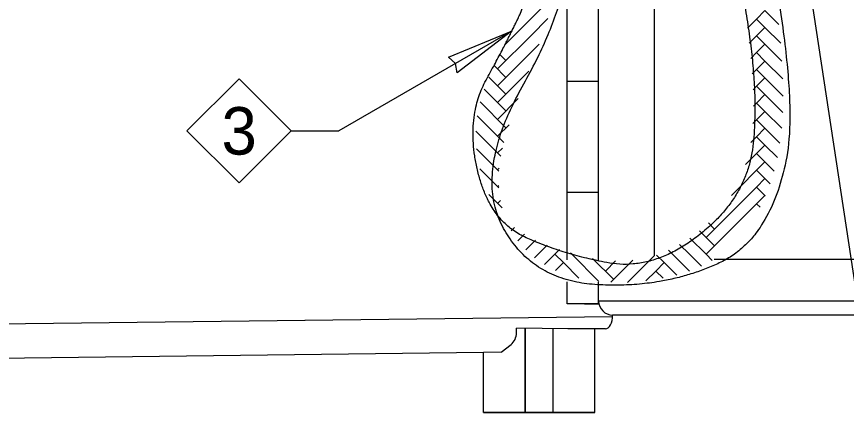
# Model space of a CAD drawing. Extents: x 99862 to 104211, y 98939 to 102076.
# Drawn here: x 100786.5 to 101065.9, y 100216.7 to 100355 of the extents above; entities that cross this region are included whole.
import ezdxf

# ---------------------------------------------------------------- set-up
doc = ezdxf.new("R2010")
doc.units = 0
for name, color, linetype in [('Level 1', 7, 'Continuous'), ('Level 12', 7, 'Continuous'), ('Level 15', 7, 'Continuous'), ('Level 16', 7, 'Continuous'), ('Level 17', 7, 'Continuous'), ('Level 20', 7, 'Continuous'), ('Level 23', 7, 'Continuous'), ('Level 3', 7, 'Continuous'), ('Level 30', 7, 'Continuous')]:
    doc.layers.add(name, color=color, linetype=linetype)

msp = doc.modelspace()

# ---------------------------------------------------------------- linework, layer by layer
at = {"layer": 'Level 1'}
for p, q in [((101001.26, 100274.46), (101001.26, 101063.37)), ((101638.77, 100273.26), (101021.35, 100273.26)), ((101657.52, 100259.2), (100982.51, 100259.2)), ((101652.84, 100254.51), (100987.19, 100254.51))]:
    msp.add_line(p, q, dxfattribs=at)
msp.add_arc((100987.19, 100259.2), 4.69, 180, 270, dxfattribs=at)
at = {"layer": 'Level 12'}
for p, q in [((100982.42, 100272.95), (100982.42, 101082.68)), ((100971.86, 100273.16), (100971.86, 100378.32)), ((100971.86, 100333.28), (100982.42, 100333.28)), ((100982.42, 100295.78), (100971.86, 100295.78)), ((100971.86, 100258.28), (100971.86, 100265.74)), ((100982.42, 100258.28), (100982.42, 100265.6)), ((100975.44, 100258.28), (100971.86, 100258.28)), ((100982.42, 100258.28), (100971.86, 100258.28)), ((100982.42, 100258.28), (100975.44, 100258.28)), ((100977.74, 100258.28), (100982.42, 100258.28))]:
    msp.add_line(p, q, dxfattribs=at)
at = {"layer": 'Level 15'}
for p, q in [((101040.62, 100450.12), (101090.56, 100120.77)), ((100953.16, 100350.13), (100894.97, 100316.54)), ((100878.97, 100316.54), (100894.97, 100316.54))]:
    msp.add_line(p, q, dxfattribs=at)
msp.add_lwpolyline([(100953.16, 100350.13), (100934.88, 100336.13), (100934.3, 100339.25), (100931.9, 100341.3)], close=True, dxfattribs=at)
at = {"layer": 'Level 16'}
for p, q in [((100965.43, 100360.01), (100959.77, 100354.35)), ((101035.67, 100354.18), (101038.5, 100357.01)), ((101043.2, 100352.3), (101038.5, 100357.01)), ((100950.81, 100345.39), (100959.77, 100354.35)), ((100965.43, 100354.35), (100959.77, 100348.7)), ((100965.43, 100354.35), (100965.44, 100354.37)), ((100965.43, 100354.35), (100965.44, 100354.34)), ((101035.67, 100354.18), (101032.6, 100351.11)), ((101035.67, 100354.18), (101038.5, 100351.35)), ((101035.67, 100348.52), (101038.5, 100351.35)), ((101043.83, 100346.02), (101038.5, 100351.35)), ((100948.46, 100337.38), (100959.77, 100348.7)), ((101035.67, 100348.52), (101033.23, 100346.08)), ((101035.67, 100348.52), (101038.5, 100345.7)), ((100962.46, 100345.73), (100959.77, 100343.04)), ((101035.67, 100342.87), (101038.5, 100345.7)), ((101044.22, 100339.97), (101038.5, 100345.7)), ((100948.46, 100331.73), (100959.77, 100343.04)), ((100951.29, 100340.21), (100949.21, 100342.29)), ((101035.67, 100342.87), (101033.76, 100340.95)), ((101035.67, 100342.87), (101038.5, 100340.04)), ((100951.29, 100334.55), (100947.33, 100338.51)), ((101035.67, 100337.21), (101038.5, 100340.04)), ((101044.53, 100334.01), (101038.5, 100340.04)), ((100948.46, 100326.07), (100959.01, 100336.62)), ((101035.67, 100337.21), (101034.18, 100335.72)), ((101035.67, 100337.21), (101038.5, 100334.38)), ((100951.29, 100328.9), (100945.56, 100334.63)), ((101035.67, 100331.55), (101038.5, 100334.38)), ((101044.62, 100328.26), (101038.5, 100334.38)), ((100951.29, 100323.24), (100943.95, 100330.58)), ((101035.67, 100331.55), (101034.5, 100330.38)), ((101035.67, 100331.55), (101038.5, 100328.73)), ((100948.46, 100320.41), (100955.45, 100327.41)), ((101035.67, 100325.9), (101038.5, 100328.73)), ((101044.49, 100322.73), (101038.5, 100328.73)), ((100951.29, 100317.58), (100942.6, 100326.27)), ((101035.67, 100325.9), (101034.61, 100324.83)), ((101035.67, 100325.9), (101038.5, 100323.07)), ((100950.56, 100312.65), (100941.62, 100321.59)), ((101035.67, 100320.24), (101038.5, 100323.07)), ((101044.13, 100317.44), (101038.5, 100323.07)), ((100948.46, 100314.76), (100952.32, 100318.62)), ((101035.67, 100320.24), (101034.41, 100318.98)), ((101035.67, 100320.24), (101038.5, 100317.41)), ((100949.54, 100308.01), (100941.15, 100316.4)), ((101035.67, 100314.58), (101038.5, 100317.41)), ((101043.55, 100312.36), (101038.5, 100317.41)), ((101035.67, 100314.58), (101033.7, 100312.61)), ((101035.67, 100314.58), (101038.5, 100311.75)), ((100948.9, 100303), (100941.36, 100310.54)), ((100948.46, 100309.1), (100950.1, 100310.74)), ((101035.67, 100308.93), (101038.5, 100311.76)), ((101042.73, 100307.52), (101038.5, 100311.76)), ((101035.67, 100308.93), (101031.97, 100305.23)), ((101035.67, 100308.93), (101038.5, 100306.1)), ((101035.67, 100303.27), (101038.5, 100306.1)), ((101041.63, 100302.97), (101038.5, 100306.1)), ((100948.88, 100297.37), (100942.48, 100303.77)), ((100948.46, 100303.44), (100948.99, 100303.97)), ((101035.67, 100303.27), (101030.01, 100297.61)), ((101035.67, 100303.27), (101038.5, 100300.44)), ((101035.67, 100297.61), (101038.5, 100300.44)), ((101040.29, 100298.65), (101038.5, 100300.44)), ((100948.46, 100297.79), (100948.84, 100298.17)), ((101027.18, 100294.78), (101030.01, 100297.61)), ((101035.67, 100297.61), (101030.01, 100291.96)), ((101035.67, 100297.61), (101038.5, 100294.78)), ((100949.97, 100290.62), (100945.5, 100295.09)), ((100948.46, 100292.13), (100949.42, 100293.09)), ((101035.67, 100291.96), (101038.5, 100294.78)), ((101038.67, 100294.61), (101038.5, 100294.78)), ((101018.7, 100280.64), (101030.01, 100291.96)), ((101035.67, 100291.96), (101030.01, 100286.3)), ((101035.67, 100291.96), (101036.83, 100290.79)), ((101018.7, 100274.99), (101030.01, 100286.3)), ((101021.53, 100283.47), (101019.46, 100285.53)), ((100953.08, 100282.91), (100954.21, 100284.03)), ((101021.53, 100277.81), (101016.46, 100282.88)), ((100955.33, 100279.5), (100957.55, 100281.72)), ((100957.96, 100276.47), (100961.22, 100279.73)), ((101018.7, 100274.99), (101013.22, 100280.46)), ((100965.17, 100278.03), (100962.13, 100274.99)), ((100967.79, 100274.99), (100969.35, 100276.54)), ((101007.39, 100274.99), (101006.04, 100276.33)), ((101013.04, 100274.99), (101009.75, 100278.27)), ((100960.95, 100273.8), (100962.13, 100274.99)), ((100962.13, 100274.99), (100962.13, 100274.99)), ((100967.79, 100274.99), (100964.3, 100271.5)), ((100967.79, 100274.99), (100970.62, 100272.16)), ((100967.79, 100274.99), (100967.79, 100274.99)), ((100973.45, 100274.99), (100973.04, 100275.39)), ((100982.6, 100265.83), (100973.45, 100274.99)), ((100987.59, 100266.5), (100980.48, 100273.61)), ((101001.19, 100274.45), (100996.07, 100269.33)), ((101002, 100274.71), (101004.56, 100272.16)), ((101013.1, 100269.28), (101007.39, 100274.99)), ((101017.1, 100270.93), (101013.04, 100274.99)), ((101020.77, 100272.91), (101018.7, 100274.99)), ((100968.02, 100269.56), (100970.62, 100272.16)), ((100975.82, 100266.95), (100970.62, 100272.16)), ((100984.76, 100269.33), (100988.19, 100272.76)), ((100986.63, 100265.54), (100994.05, 100272.97)), ((101001.73, 100269.33), (101004.56, 100272.16)), ((101008.78, 100267.93), (101004.56, 100272.16)), ((100992.26, 100265.52), (100996.07, 100269.33)), ((101001.73, 100269.33), (100998.41, 100266.01)), ((101001.73, 100269.33), (101004.17, 100266.89))]:
    msp.add_line(p, q, dxfattribs=at)
at = {"layer": 'Level 17'}
for p, q in [((100957.78, 100221.7), (100957.78, 100250.05)), ((100957.78, 100250.05), (100957.78, 100221.7)), ((100981.22, 100221.7), (100981.22, 100249.85)), ((100976.53, 100221.7), (100976.53, 100221.7)), ((100981.22, 100221.7), (100981.22, 100221.7))]:
    msp.add_line(p, q, dxfattribs=at)
for points in [[(100943.72, 100221.7), (100981.22, 100221.7), (100981.22, 100249.85)], [(100981.22, 100221.7), (100967.16, 100221.7), (100967.16, 100249.94)], [(100967.16, 100221.7), (100967.16, 100249.94)], [(100957.78, 100221.7), (100943.72, 100221.7), (100943.72, 100241.92)], [(100943.72, 100221.7), (100943.72, 100241.92)], [(100976.53, 100221.7), (100948.41, 100221.7), (100948.41, 100221.7)], [(100948.41, 100221.7), (100948.41, 100221.7), (100948.41, 100221.7)], [(100948.41, 100221.7), (100953.09, 100221.7), (100953.09, 100221.7)], [(100957.78, 100221.7), (100957.78, 100221.7), (100953.09, 100221.7), (100953.09, 100221.7)], [(100967.16, 100221.7), (100971.84, 100221.7), (100971.84, 100221.7)], [(100971.84, 100221.7), (100971.84, 100221.7), (100971.84, 100221.7)], [(100971.84, 100221.7), (100976.53, 100221.7), (100976.53, 100221.7)]]:
    msp.add_lwpolyline(points, dxfattribs=at)
at = {"layer": 'Level 20'}
msp.add_lwpolyline([(100861.42, 100334.09), (100878.97, 100316.54), (100861.42, 100298.99), (100843.86, 100316.54)], close=True, dxfattribs=at)
at = {"layer": 'Level 23'}
for points in [[(101028.54, 100431.2), (101050.94, 100337.83), (101041.04, 100280.1), (101003.96, 100263.4), (100959.71, 100266.09), (100940.55, 100302.69), (100973.71, 100361.4), (100973.71, 100410.09), (100953.26, 100439.27)], [(101022.51, 100431.34), (101022.51, 100411.27), (101028.58, 100378.1), (101036.34, 100329.81), (101032.71, 100294.45), (101000.82, 100269.14), (100969.7, 100275.19), (100945.53, 100286.37), (100937.68, 100321.13), (100951.88, 100346.82), (100960.53, 100365.6), (100960.53, 100410.64), (100947.62, 100432.82)]]:
    msp.add_open_spline(points, degree=2, dxfattribs=at)
at = {"layer": 'Level 3'}
for p, q in [((100640.46, 100249.88), (100987.18, 100254.07)), ((100954.83, 100248.53), (100954.83, 100250.08)), ((100972.11, 100249.88), (100954.83, 100250.08)), ((100984.77, 100249.85), (100972.11, 100249.85)), ((100949.63, 100241.99), (100953.02, 100244.63)), ((100943.76, 100241.92), (100654.28, 100238.42)), ((100949.63, 100241.99), (100943.78, 100241.92))]:
    msp.add_line(p, q, dxfattribs=at)
for centre, major_axis, ratio, start_param, end_param in [((100984.79, 100254.54), (0, -4.69), 0.51393, 6.27698, 7.847777), ((100950.8, 100248.53), (-0.06, -4.69), 0.857815, 0.598947, 1.581153)]:
    msp.add_ellipse(centre, major_axis=major_axis, ratio=ratio, start_param=start_param, end_param=end_param, dxfattribs=at)
at = {"layer": 'Level 30'}
for points in [[(101050.83, 100550.12), (101053.01, 100531.91), (101055.8, 100512.03), (101061.94, 100480.78), (101064.55, 100469.36), (101069.14, 100452.77), (101070.79, 100447.34), (101074.32, 100436.74), (101076.22, 100431.58), (101086.28, 100406.47), (101096.21, 100388.64), (101118.68, 100358.15), (101131.21, 100345.5), (101147.75, 100333.34), (101151.1, 100331.09), (101157.89, 100326.95), (101161.32, 100325.06), (101171.72, 100319.88), (101178.81, 100317.06), (101200.44, 100310.21), (101215.37, 100307.75), (101238.15, 100305.83), (101245.81, 100305.48), (101261.19, 100305.15), (101268.91, 100305.16), (101288.28, 100305.5), (101299.75, 100306.02), (101310.29, 100306.65)], [(101048.01, 100548.43), (101052.16, 100514.02), (101067.9, 100415), (101144.87, 100312.33), (101236.87, 100300.57), (101293.2, 100302.62), (101310.29, 100303.65)]]:
    msp.add_open_spline(points, degree=3, dxfattribs=at)

# ---------------------------------------------------------------- texts
at = {"layer": 'Level 20'}
msp.add_text('3', height=16, dxfattribs=at).set_placement((100855.51, 100308.54))

doc.saveas('drawing.dxf')
